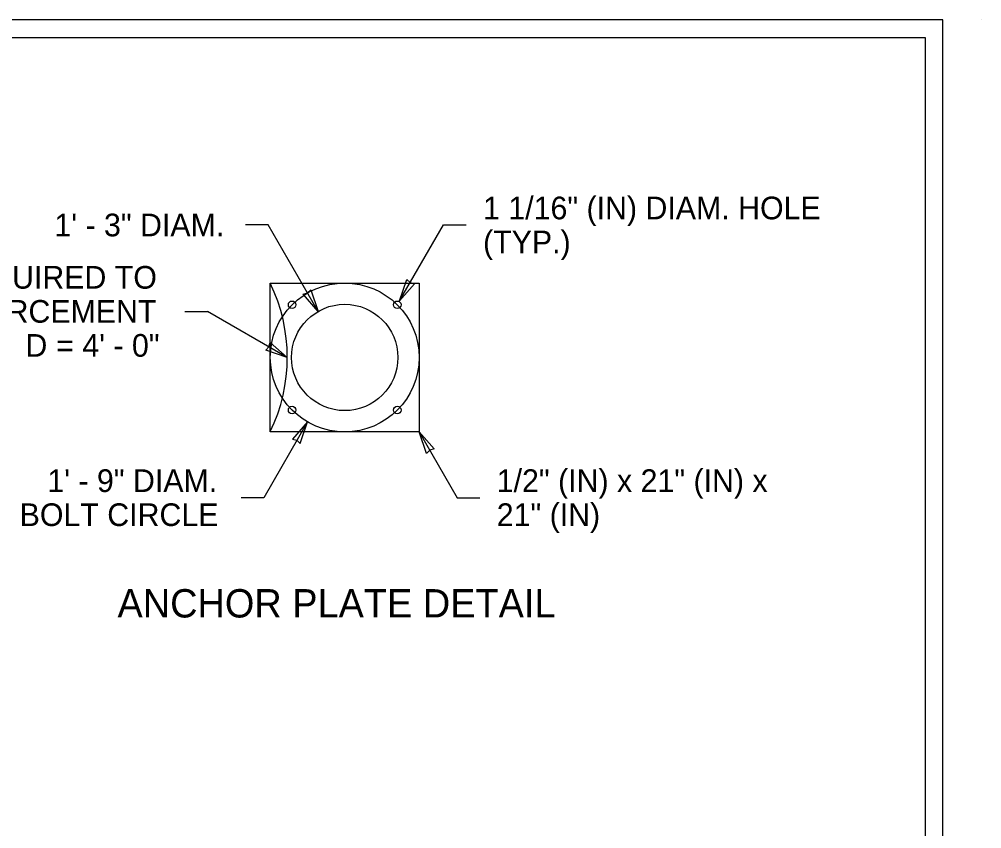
# Model space of a CAD drawing. Extents: x 99888 to 103177, y 100000 to 102076.
# Drawn here: x 102498 to 103177, y 101505 to 102076 of the extents above; entities that cross this region are included whole.
import ezdxf

# ---------------------------------------------------------------- set-up
doc = ezdxf.new("R2010")
doc.units = 0
for name, color, linetype in [('Level 15', 7, 'Continuous'), ('Level 20', 7, 'Continuous'), ('Level 23', 7, 'Continuous'), ('Level 60', 7, 'Continuous'), ('SH_GI_PlotLimits', 7, 'Continuous'), ('SH_GI_SheetBorder', 7, 'Continuous')]:
    doc.layers.add(name, color=color, linetype=linetype)

msp = doc.modelspace()

# ---------------------------------------------------------------- linework, layer by layer
at = {"layer": 'Level 15'}
for p, q in [((102674.02, 101930.92), (102658.02, 101930.92)), ((102674.02, 101930.92), (102658.02, 101930.92)), ((102709.2, 101869.98), (102674.02, 101930.92)), ((102709.2, 101869.98), (102674.02, 101930.92)), ((102766.67, 101877.39), (102797.58, 101930.92)), ((102766.67, 101877.39), (102797.58, 101930.92)), ((102797.58, 101930.92), (102813.58, 101930.92)), ((102797.58, 101930.92), (102813.58, 101930.92)), ((102615.16, 101870), (102631.16, 101870)), ((102615.16, 101870), (102631.16, 101870)), ((102687.45, 101837.5), (102631.16, 101870)), ((102687.45, 101837.5), (102631.16, 101870)), ((102701.7, 101792.04), (102670.85, 101738.6)), ((102701.7, 101792.04), (102670.85, 101738.6)), ((102780.45, 101785), (102807.24, 101738.6)), ((102780.45, 101785), (102807.24, 101738.6)), ((102670.85, 101738.6), (102654.85, 101738.6)), ((102670.85, 101738.6), (102654.85, 101738.6)), ((102807.24, 101738.6), (102823.24, 101738.6)), ((102807.24, 101738.6), (102823.24, 101738.6))]:
    msp.add_line(p, q, dxfattribs=at)
for points in [[(102766.67, 101877.39), (102771.86, 101892.55), (102774.17, 101890.37), (102777.2, 101889.46)], [(102766.67, 101877.39), (102771.86, 101892.55), (102774.17, 101890.37), (102777.2, 101889.46)], [(102709.2, 101869.98), (102698.67, 101882.06), (102701.71, 101882.97), (102704.01, 101885.14)], [(102709.2, 101869.98), (102698.67, 101882.06), (102701.71, 101882.97), (102704.01, 101885.14)], [(102687.45, 101837.5), (102672.29, 101842.7), (102674.47, 101845), (102675.38, 101848.04)], [(102701.7, 101792.04), (102691.17, 101779.96), (102694.21, 101779.05), (102696.51, 101776.88)], [(102701.7, 101792.04), (102691.17, 101779.96), (102694.21, 101779.05), (102696.51, 101776.88)], [(102780.45, 101785), (102790.99, 101772.93), (102787.95, 101772.02), (102785.65, 101769.84)]]:
    msp.add_lwpolyline(points, close=True, dxfattribs=at)
msp.add_circle((102727.95, 101837.5), 52.5, dxfattribs=at)
msp.add_circle((102727.95, 101837.5), 52.5, dxfattribs=at)
at = {"layer": 'Level 23'}
for p, q in [((102675.45, 101890), (102780.45, 101890)), ((102675.45, 101785), (102675.45, 101890)), ((102780.45, 101890), (102780.45, 101785)), ((102780.45, 101785), (102675.45, 101785))]:
    msp.add_line(p, q, dxfattribs=at)
for centre, radius in [((102690.83, 101874.63), 2.66), ((102690.83, 101874.63), 2.66), ((102765.08, 101874.63), 2.66), ((102765.08, 101874.63), 2.66), ((102727.95, 101837.5), 37.5), ((102690.83, 101800.38), 2.66), ((102690.83, 101800.38), 2.66), ((102765.08, 101800.38), 2.66), ((102765.08, 101800.38), 2.66)]:
    msp.add_circle(centre, radius, dxfattribs=at)
msp.add_arc((102567.45, 101837.5), 120, 334.15807, 25.84193, dxfattribs=at)
msp.add_arc((102567.45, 101837.5), 120, 334.15807, 25.84193, dxfattribs=at)
at = {"layer": 'Level 60'}
msp.add_line((103177.5, 102076), (103177.5, 102076), dxfattribs=at)
at = {"layer": 'SH_GI_PlotLimits'}
msp.add_lwpolyline([(99888.5, 100000), (103150, 100000), (103150, 102075.5), (99888.5, 102075.5)], close=True, dxfattribs=at)
msp.add_lwpolyline([(99888.5, 100000), (103150, 100000), (103150, 102075.5), (99888.5, 102075.5)], close=True, dxfattribs=at)
at = {"layer": 'SH_GI_SheetBorder'}
for p, q in [((100024.39, 102063.15), (103137.64, 102063.15)), ((100024.39, 102063.15), (103137.64, 102063.15)), ((103137.64, 102063.15), (103137.64, 100012.35)), ((103137.64, 102063.15), (103137.64, 100012.35))]:
    msp.add_line(p, q, dxfattribs=at)

# ---------------------------------------------------------------- texts
at = {"layer": 'Level 20'}
for s, height, p in [('1 1/16" (IN) DIAM. HOLE ', 16, (102825.58, 101934.92)), ('1\' - 3" DIAM.', 16, (102523.09, 101922.92)), ('(TYP.)', 16, (102825.58, 101910.92)), ('NOTCH AS REQUIRED TO', 16, (102330.32, 101886)), ('CLEAR SHAFT REINFORCEMENT', 16, (102255.14, 101862)), (' D', 16, (102496.69, 101838)), (' = 4\' - 0"', 16, (102518.42, 101838)), ('1\' - 9" DIAM.', 16, (102518.11, 101742.6)), ('1/2" (IN) x 21" (IN) x ', 16, (102835.24, 101742.6)), ('BOLT CIRCLE', 16, (102498.56, 101718.6)), ('21" (IN)', 16, (102835.24, 101718.6)), ('ANCHOR PLATE DETAIL', 20, (102567.6, 101654.1))]:
    msp.add_text(s, height=height, dxfattribs=at).set_placement(p)

doc.saveas('drawing.dxf')
